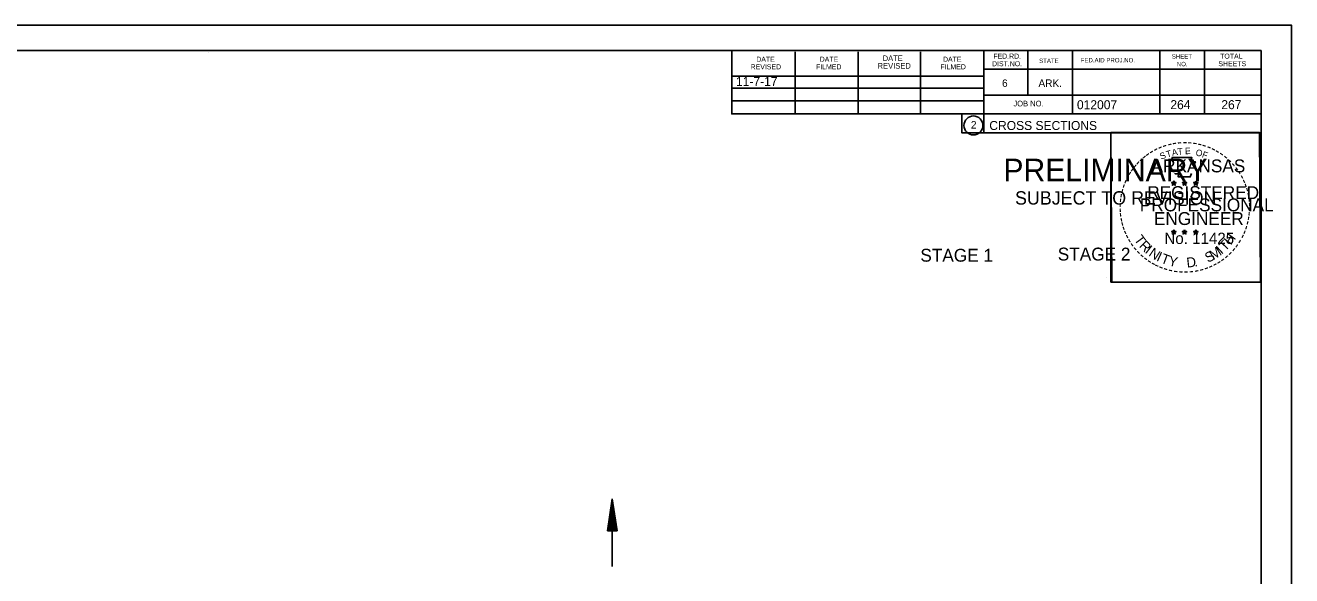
# Model space of a CAD drawing. Extents: x 1374311 to 1383814, y 384102 to 406278.
# Drawn here: x 1382687 to 1382883.8, y 387380.4 to 387465.9 of the extents above; entities that cross this region are included whole.
import ezdxf

# ---------------------------------------------------------------- set-up
doc = ezdxf.new("R2010")
doc.units = 0
for name, color, linetype in [('R_Border', 7, 'Continuous'), ('R_Border PE', 7, 'Continuous'), ('R_Border Prem', 7, 'Continuous'), ('R_Draft', 7, 'Continuous'), ('R_Fin Surface', 7, 'Continuous'), ('R_No Plot', 7, 'Continuous'), ('R_Water', 7, 'Continuous')]:
    doc.layers.add(name, color=color, linetype=linetype)

msp = doc.modelspace()

# ---------------------------------------------------------------- linework, layer by layer
at = {"layer": 'R_Border'}
for p, q in [((1382562.86, 387462.05), (1382879.04, 387462.05)), ((1382796.78, 387452.17), (1382796.78, 387462.05)), ((1382835.94, 387462.05), (1382835.94, 387449.25)), ((1382842.78, 387462.05), (1382842.78, 387455.11)), ((1382849.72, 387462.05), (1382849.72, 387452.17)), ((1382863.3, 387462.05), (1382863.3, 387452.17)), ((1382870.24, 387462.05), (1382870.24, 387452.17)), ((1382879.04, 387256.59), (1382879.04, 387462.05)), ((1382715.38, 387461.79), (1382715.38, 387461.79)), ((1382715.38, 387461.79), (1382715.38, 387461.79)), ((1382806.64, 387452.17), (1382806.64, 387461.85)), ((1382816.4, 387452.17), (1382816.4, 387461.85)), ((1382826.08, 387452.17), (1382826.08, 387461.85)), ((1382879.04, 387459.11), (1382835.94, 387459.11)), ((1382879.04, 387459.13), (1382879.04, 387459.13)), ((1382796.78, 387458.03), (1382835.94, 387458.03)), ((1382796.78, 387456.17), (1382835.94, 387456.17)), ((1382796.78, 387452.17), (1382796.78, 387454.23)), ((1382796.78, 387454.23), (1382835.94, 387454.23)), ((1382879.04, 387455.11), (1382835.94, 387455.11)), ((1382838.9, 387455.11), (1382879.04, 387455.11)), ((1382879.04, 387452.17), (1382796.78, 387452.17)), ((1382835.94, 387449.25), (1382879.04, 387449.25))]:
    msp.add_line(p, q, dxfattribs=at)
msp.add_circle((1382834.33, 387450.39), 1.47, dxfattribs=at)
at = {"layer": 'R_Border PE'}
for p, q in [((1382865.13, 387441.51), (1382865.47, 387441.4)), ((1382865.13, 387441.51), (1382865.38, 387441.46)), ((1382865.13, 387441.51), (1382865.36, 387441.39)), ((1382865.26, 387441.1), (1382865.47, 387441.4)), ((1382865.26, 387441.1), (1382865.38, 387441.34)), ((1382865.26, 387441.1), (1382865.47, 387441.32)), ((1382865.47, 387441.76), (1382865.43, 387441.51)), ((1382865.47, 387441.4), (1382865.47, 387441.76)), ((1382865.47, 387441.76), (1382865.52, 387441.51)), ((1382865.82, 387441.51), (1382865.47, 387441.4)), ((1382865.69, 387441.1), (1382865.47, 387441.4)), ((1382865.69, 387441.1), (1382865.47, 387441.31)), ((1382865.82, 387441.51), (1382865.54, 387441.46)), ((1382865.69, 387441.1), (1382865.55, 387441.39)), ((1382865.82, 387441.51), (1382865.62, 387441.41)), ((1382866.8, 387441.51), (1382867.14, 387441.4)), ((1382866.8, 387441.51), (1382867.05, 387441.46)), ((1382866.8, 387441.51), (1382867.03, 387441.39)), ((1382866.93, 387441.1), (1382867.14, 387441.4)), ((1382866.93, 387441.1), (1382867.05, 387441.34)), ((1382866.93, 387441.1), (1382867.14, 387441.32)), ((1382867.14, 387441.76), (1382867.1, 387441.51)), ((1382867.14, 387441.4), (1382867.14, 387441.76)), ((1382867.14, 387441.76), (1382867.19, 387441.51)), ((1382867.49, 387441.51), (1382867.14, 387441.4)), ((1382867.36, 387441.1), (1382867.14, 387441.4)), ((1382867.36, 387441.1), (1382867.14, 387441.31)), ((1382867.49, 387441.51), (1382867.21, 387441.46)), ((1382867.36, 387441.1), (1382867.22, 387441.39)), ((1382867.49, 387441.51), (1382867.29, 387441.41)), ((1382868.56, 387441.5), (1382868.91, 387441.38)), ((1382868.56, 387441.5), (1382868.81, 387441.45)), ((1382868.56, 387441.5), (1382868.8, 387441.37)), ((1382868.69, 387441.09), (1382868.91, 387441.38)), ((1382868.69, 387441.09), (1382868.82, 387441.33)), ((1382868.69, 387441.09), (1382868.91, 387441.3)), ((1382868.91, 387441.75), (1382868.87, 387441.5)), ((1382868.91, 387441.38), (1382868.91, 387441.75)), ((1382868.91, 387441.75), (1382868.96, 387441.5)), ((1382869.26, 387441.5), (1382868.91, 387441.38)), ((1382869.12, 387441.09), (1382868.91, 387441.38)), ((1382869.12, 387441.09), (1382868.91, 387441.3)), ((1382869.26, 387441.5), (1382868.97, 387441.45)), ((1382869.12, 387441.09), (1382868.98, 387441.38)), ((1382869.26, 387441.5), (1382869.05, 387441.39)), ((1382865.12, 387433.93), (1382865.47, 387433.82)), ((1382865.12, 387433.93), (1382865.37, 387433.89)), ((1382865.12, 387433.93), (1382865.36, 387433.81)), ((1382865.25, 387433.53), (1382865.47, 387433.82)), ((1382865.25, 387433.53), (1382865.38, 387433.77)), ((1382865.25, 387433.53), (1382865.47, 387433.74)), ((1382865.47, 387434.19), (1382865.43, 387433.94)), ((1382865.47, 387433.82), (1382865.47, 387434.19)), ((1382865.47, 387434.19), (1382865.52, 387433.94)), ((1382865.82, 387433.93), (1382865.47, 387433.82)), ((1382865.68, 387433.53), (1382865.47, 387433.82)), ((1382865.68, 387433.53), (1382865.47, 387433.74)), ((1382865.82, 387433.93), (1382865.53, 387433.89)), ((1382865.68, 387433.53), (1382865.55, 387433.82)), ((1382865.82, 387433.93), (1382865.61, 387433.83)), ((1382866.79, 387433.93), (1382867.14, 387433.82)), ((1382866.79, 387433.93), (1382867.04, 387433.89)), ((1382866.79, 387433.93), (1382867.03, 387433.81)), ((1382866.92, 387433.53), (1382867.14, 387433.82)), ((1382866.92, 387433.53), (1382867.05, 387433.77)), ((1382866.92, 387433.53), (1382867.14, 387433.74)), ((1382867.14, 387434.19), (1382867.1, 387433.94)), ((1382867.14, 387433.82), (1382867.14, 387434.19)), ((1382867.14, 387434.19), (1382867.19, 387433.94)), ((1382867.49, 387433.93), (1382867.14, 387433.82)), ((1382867.35, 387433.53), (1382867.14, 387433.82)), ((1382867.35, 387433.53), (1382867.14, 387433.74)), ((1382867.49, 387433.93), (1382867.2, 387433.89)), ((1382867.35, 387433.53), (1382867.22, 387433.82)), ((1382867.49, 387433.93), (1382867.28, 387433.83)), ((1382868.56, 387433.92), (1382868.91, 387433.81)), ((1382868.56, 387433.92), (1382868.81, 387433.88)), ((1382868.56, 387433.92), (1382868.79, 387433.8)), ((1382868.69, 387433.52), (1382868.91, 387433.81)), ((1382868.69, 387433.52), (1382868.82, 387433.76)), ((1382868.69, 387433.52), (1382868.9, 387433.73)), ((1382868.91, 387434.18), (1382868.87, 387433.93)), ((1382869.12, 387433.52), (1382868.9, 387433.73)), ((1382868.91, 387433.81), (1382868.91, 387434.18)), ((1382868.91, 387434.18), (1382868.96, 387433.93)), ((1382869.25, 387433.92), (1382868.91, 387433.81)), ((1382869.12, 387433.52), (1382868.91, 387433.81)), ((1382869.25, 387433.92), (1382868.97, 387433.88)), ((1382869.12, 387433.52), (1382868.98, 387433.81)), ((1382869.25, 387433.92), (1382869.05, 387433.82))]:
    msp.add_line(p, q, dxfattribs=at)
for points in [[(1382865.17, 387445.39), (1382865.44, 387444.56)], [(1382868.68, 387444.46), (1382868.82, 387444.75), (1382868.13, 387444.72), (1382868.28, 387445.39), (1382865.17, 387445.39)], [(1382865.66, 387442.96), (1382865.66, 387442.88), (1382866.22, 387442.86), (1382866.17, 387442.38), (1382868.04, 387442.38), (1382868.24, 387442.92)], [(1382865.47, 387441.76), (1382865.69, 387441.1), (1382865.13, 387441.51), (1382865.82, 387441.51), (1382865.26, 387441.1), (1382865.47, 387441.76)], [(1382867.14, 387441.76), (1382867.36, 387441.1), (1382866.8, 387441.51), (1382867.49, 387441.51), (1382866.93, 387441.1), (1382867.14, 387441.76)], [(1382868.91, 387441.75), (1382869.12, 387441.09), (1382868.56, 387441.5), (1382869.26, 387441.5), (1382868.69, 387441.09), (1382868.91, 387441.75)], [(1382865.47, 387434.19), (1382865.68, 387433.53), (1382865.12, 387433.93), (1382865.82, 387433.93), (1382865.25, 387433.53), (1382865.47, 387434.19)], [(1382867.14, 387434.19), (1382867.35, 387433.53), (1382866.79, 387433.93), (1382867.49, 387433.93), (1382866.92, 387433.53), (1382867.14, 387434.19)], [(1382868.91, 387434.18), (1382869.12, 387433.52), (1382868.56, 387433.92), (1382869.25, 387433.92), (1382868.69, 387433.52), (1382868.91, 387434.18)]]:
    msp.add_lwpolyline(points, dxfattribs=at)
for centre, radius in [((1382865.47, 387441.4), 0.172), ((1382865.47, 387441.4), 0.145), ((1382865.47, 387441.4), 0.116), ((1382865.47, 387441.4), 0.0991), ((1382865.47, 387441.4), 0.0747), ((1382865.47, 387441.4), 0.0495), ((1382865.47, 387441.4), 0.0296), ((1382867.14, 387441.4), 0.172), ((1382867.14, 387441.4), 0.145), ((1382867.14, 387441.4), 0.116), ((1382867.14, 387441.4), 0.0991), ((1382867.14, 387441.4), 0.0747), ((1382867.14, 387441.4), 0.0495), ((1382867.14, 387441.4), 0.0296), ((1382868.91, 387441.38), 0.172), ((1382868.91, 387441.38), 0.145), ((1382868.91, 387441.38), 0.116), ((1382868.91, 387441.38), 0.0991), ((1382868.91, 387441.38), 0.0747), ((1382868.91, 387441.38), 0.0495), ((1382868.91, 387441.38), 0.0296), ((1382865.47, 387433.82), 0.172), ((1382865.47, 387433.82), 0.145), ((1382865.47, 387433.82), 0.116), ((1382865.47, 387433.82), 0.0991), ((1382865.47, 387433.82), 0.0747), ((1382865.47, 387433.82), 0.0495), ((1382865.47, 387433.82), 0.0296), ((1382867.14, 387433.82), 0.172), ((1382867.14, 387433.82), 0.145), ((1382867.14, 387433.82), 0.116), ((1382867.14, 387433.82), 0.0991), ((1382867.14, 387433.82), 0.0747), ((1382867.14, 387433.82), 0.0495), ((1382867.14, 387433.82), 0.0296), ((1382868.91, 387433.81), 0.172), ((1382868.91, 387433.81), 0.145), ((1382868.91, 387433.81), 0.116), ((1382868.91, 387433.81), 0.0991), ((1382868.91, 387433.81), 0.0747), ((1382868.91, 387433.81), 0.0495), ((1382868.91, 387433.81), 0.0296)]:
    msp.add_circle(centre, radius, dxfattribs=at)
at = {"layer": 'R_Draft'}
for p, q in [((1382777.44, 387387.38), (1382778.19, 387392.38)), ((1382777.57, 387387.38), (1382778.19, 387391.55)), ((1382778.94, 387387.38), (1382778.19, 387392.38)), ((1382778.82, 387387.38), (1382778.19, 387391.55)), ((1382777.69, 387387.38), (1382778.19, 387390.69)), ((1382777.82, 387387.38), (1382778.19, 387389.85)), ((1382778.69, 387387.38), (1382778.19, 387390.69)), ((1382778.56, 387387.38), (1382778.19, 387389.85)), ((1382777.44, 387387.38), (1382778.94, 387387.38)), ((1382777.95, 387387.38), (1382778.19, 387389.01)), ((1382778.07, 387387.38), (1382778.19, 387388.17)), ((1382778.44, 387387.38), (1382778.19, 387389.01)), ((1382778.31, 387387.38), (1382778.19, 387388.17))]:
    msp.add_line(p, q, dxfattribs=at)
at = {"layer": 'R_No Plot'}
for p, q in [((1382550.46, 387465.95), (1382883.79, 387465.95)), ((1382855.08, 387426.8), (1382855.08, 387426.8))]:
    msp.add_line(p, q, dxfattribs=at)
for points in [[(1382550.45, 387465.95), (1382883.79, 387465.95), (1382883.79, 387252.61), (1382550.45, 387252.61)], [(1382796.78, 387462.05), (1382796.78, 387452.17), (1382832.51, 387452.17), (1382832.51, 387449.25), (1382855.71, 387449.25), (1382855.71, 387426.04), (1382879.04, 387426.04), (1382879.04, 387256.59), (1382562.86, 387256.59), (1382562.86, 387462.05)], [(1382855.71, 387449.28), (1382878.81, 387449.28), (1382878.93, 387426.04), (1382855.83, 387426.04)]]:
    msp.add_lwpolyline(points, close=True, dxfattribs=at)
at = {"layer": 'R_Water'}
msp.add_line((1382778.19, 387381.87), (1382778.19, 387392.38), dxfattribs=at)

# ---------------------------------------------------------------- texts
at = {"layer": 'R_Border'}
for s, height, p in [('DATE', 0.782, (1382800.58, 387460.29)), ('DATE', 0.782, (1382810.44, 387460.29)), ('REVISED', 0.879, (1382819.44, 387459.21)), ('DATE', 0.879, (1382820.22, 387460.39)), ('DATE', 0.782, (1382829.6, 387460.29)), ('DIST.NO.', 0.782, (1382837.22, 387459.59)), ('FED.RD.', 0.782, (1382837.42, 387460.77)), ('STATE', 0.684, (1382844.54, 387460.09)), ('FED.AID PROJ.NO.', 0.684, (1382851, 387460.19)), ('SHEET', 0.684, (1382865.16, 387460.77)), ('NO.', 0.684, (1382865.94, 387459.59)), ('SHEETS', 0.782, (1382872.4, 387459.59)), ('TOTAL', 0.782, (1382872.68, 387460.77)), ('REVISED', 0.782, (1382799.7, 387459.11)), ('FILMED', 0.782, (1382809.86, 387459.11)), ('FILMED', 0.782, (1382829.2, 387459.11)), ('6', 1.17, (1382838.78, 387456.37)), ('ARK.', 1.172, (1382844.44, 387456.37)), ('JOB NO.', 0.879, (1382840.54, 387453.35)), ('012007', 1.4, (1382850.42, 387452.91)), ('2', 1.17, (1382833.94, 387449.9)), ('CROSS SECTIONS', 1.4, (1382836.8, 387449.68))]:
    msp.add_text(s, height=height, rotation=360, dxfattribs=at).set_placement(p)
at = {"layer": 'R_Border PE'}
for s, height, rotation, p in [('-', 1.6, 34.0636, (1382862.05, 387445.56)), ('-', 1.6, 28.7918, (1382862.65, 387445.93)), ('-', 1.6, 24.3072, (1382863.28, 387446.24)), ('-', 1.6, 19.1761, (1382863.91, 387446.51)), ('T', 1, 16.4036, (1382864.44, 387445.39)), ('-', 1.6, 13.6301, (1382864.66, 387446.75)), ('A', 1, 11.2132, (1382865.26, 387445.65)), ('-', 1.6, 10.2193, (1382865.34, 387446.92)), ('T', 1, 6.0228, (1382866.11, 387445.81)), ('-', 1.6, 5.8968, (1382866.07, 387447.03)), ('-', 1.6, 0.1862, (1382866.84, 387447.1)), ('E', 1, 0.8323, (1382867.22, 387445.92)), ('-', 1.6, 357.743, (1382867.57, 387447.08)), ('-', 1.6, 352.1617, (1382868.31, 387447.03)), ('O', 1, 350.4515, (1382868.82, 387445.71)), ('-', 1.6, 347.2049, (1382869.03, 387446.91)), ('F', 1, 340.0707, (1382869.77, 387445.48)), ('-', 1.6, 342.3362, (1382869.66, 387446.76)), ('-', 1.6, 337.8551, (1382870.4, 387446.54)), ('-', 1.6, 334.1211, (1382871.03, 387446.27)), ('-', 1.6, 329.6409, (1382871.61, 387445.98)), ('-', 1.6, 50.6142, (1382859.71, 387443.4)), ('-', 1.6, 48.423, (1382860.12, 387443.89)), ('-', 1.6, 42.9622, (1382860.56, 387444.37)), ('-', 1.6, 38.9507, (1382861, 387444.78)), ('-', 1.6, 36.2317, (1382861.47, 387445.16)), ('ARKANSAS', 2, 360, (1382862.02, 387443.1)), ('S', 1, 21.594, (1382863.52, 387445.06)), ('-', 1.6, 325.8627, (1382872.25, 387445.62)), ('-', 1.6, 320.5297, (1382872.86, 387445.2)), ('-', 1.6, 315.5786, (1382873.46, 387444.71)), ('-', 1.6, 309.8797, (1382874.03, 387444.16)), ('-', 1.6, 62.8713, (1382858.66, 387441.69)), ('-', 1.6, 58.0706, (1382858.97, 387442.31)), ('-', 1.6, 54.2325, (1382859.3, 387442.84)), ('-', 1.6, 306.6522, (1382874.56, 387443.56)), ('-', 1.4, 303.6753, (1382875.04, 387442.99)), ('-', 1.6, 299.6684, (1382875.36, 387442.38)), ('-', 1.6, 75.461, (1382857.99, 387439.74)), ('-', 1.6, 72.3945, (1382858.18, 387440.45)), ('-', 1.6, 67.7743, (1382858.4, 387441.08)), ('REGISTERED', 2, 360, (1382861.34, 387438.95)), ('DWB', 0.01, 360, (1382865.46, 387441.39)), ('DWB', 0.01, 360, (1382867.13, 387441.39)), ('DWB', 0.01, 360, (1382868.9, 387441.38)), ('-', 1.6, 294.6628, (1382875.68, 387441.77)), ('-', 1.6, 290.5728, (1382875.94, 387441.19)), ('-', 1.6, 285.1233, (1382876.18, 387440.61)), ('-', 1.6, 85.1863, (1382857.78, 387438.34)), ('-', 1.6, 81.2013, (1382857.85, 387439.03)), ('PROFESSIONAL', 2, 360, (1382860.19, 387437.04)), ('-', 1.6, 280.5493, (1382876.38, 387439.87)), ('-', 1.6, 276.5962, (1382876.54, 387439.1)), ('-', 1.6, 94.1959, (1382857.79, 387436.91)), ('-', 1.6, 89.0622, (1382857.75, 387437.63)), ('-', 1.6, 98.9479, (1382857.86, 387436.24)), ('ENGINEER', 2, 360, (1382862.38, 387434.92)), ('-', 1.6, 263.5172, (1382876.61, 387437.08)), ('-', 1.6, 274.3301, (1382876.6, 387438.38)), ('-', 1.6, 269.9407, (1382876.63, 387437.75)), ('-', 1.6, 101.7149, (1382858, 387435.51)), ('-', 1.6, 105.4578, (1382858.16, 387434.91)), ('-', 1.6, 109.0874, (1382858.37, 387434.28)), ('-', 1.6, 252.8681, (1382876.25, 387435.03)), ('-', 1.6, 255.7626, (1382876.43, 387435.75)), ('-', 1.6, 260.9953, (1382876.54, 387436.43)), ('-', 1.6, 114.0643, (1382858.63, 387433.69)), ('-', 1.6, 115.7289, (1382858.93, 387433.07)), ('-', 1.6, 120.4471, (1382859.29, 387432.48)), ('T', 1.54, 306.0406, (1382859.23, 387432.66)), ('R', 1.54, 314.005, (1382859.99, 387431.61)), ('No. 11425', 1.757, 360, (1382864.01, 387431.97)), ('DWB', 0.01, 360, (1382865.46, 387433.82)), ('DWB', 0.01, 360, (1382867.13, 387433.82)), ('DWB', 0.01, 360, (1382868.89, 387433.81)), ('T', 1.54, 46.6444, (1382873.46, 387430.75)), ('H', 1.54, 54.6088, (1382874.35, 387431.7)), ('-', 1.6, 239.0712, (1382875.37, 387432.98)), ('-', 1.6, 244.6197, (1382875.77, 387433.73)), ('-', 1.6, 247.8887, (1382876.03, 387434.36)), ('-', 1.6, 125.8934, (1382859.69, 387431.92)), ('-', 1.6, 130.7181, (1382860.15, 387431.37)), ('-', 1.6, 134.2238, (1382860.67, 387430.83)), ('I', 1.54, 321.9694, (1382860.89, 387430.68)), ('N', 1.54, 326.5002, (1382861.46, 387430.21)), ('I', 1.54, 335.3603, (1382862.67, 387429.42)), ('S', 1.54, 26.9312, (1382870.78, 387429.02)), ('M', 1.54, 32.6563, (1382871.61, 387429.43)), ('I', 1.54, 42.1136, (1382872.9, 387430.28)), ('-', 1.6, 225.7653, (1382874.06, 387431.19)), ('-', 1.6, 231.2538, (1382874.54, 387431.76)), ('-', 1.6, 233.8452, (1382874.97, 387432.32)), ('-', 1.6, 138.9338, (1382861.2, 387430.36)), ('-', 1.6, 144.6463, (1382861.75, 387429.96)), ('-', 1.6, 148.0898, (1382862.31, 387429.58)), ('-', 1.6, 151.5704, (1382862.89, 387429.26)), ('-', 1.6, 154.6002, (1382863.41, 387429.01)), ('T', 1.54, 339.8912, (1382863.33, 387429.1)), ('Y', 1.54, 347.8556, (1382864.55, 387428.65)), ('D', 1.54, 6.3969, (1382867.53, 387428.29)), ('.', 1.54, 13.7642, (1382868.72, 387428.42)), ('-', 1.6, 204.2516, (1382871.27, 387429.16)), ('-', 1.6, 207.3568, (1382871.9, 387429.48)), ('-', 1.6, 212.2491, (1382872.46, 387429.82)), ('-', 1.6, 215.7363, (1382872.99, 387430.21)), ('-', 1.6, 221.0851, (1382873.54, 387430.68)), ('-', 1.6, 158.5612, (1382864.04, 387428.76)), ('-', 1.6, 162.7983, (1382864.72, 387428.55)), ('-', 1.6, 167.5555, (1382865.44, 387428.38)), ('-', 1.6, 173.1155, (1382866.21, 387428.27)), ('-', 1.6, 176.5183, (1382866.96, 387428.22)), ('-', 1.6, 181.5918, (1382867.7, 387428.24)), ('-', 1.6, 185.8167, (1382868.51, 387428.31)), ('-', 1.6, 191.2858, (1382869.25, 387428.45)), ('-', 1.6, 195.4743, (1382869.98, 387428.64)), ('-', 1.6, 200.7184, (1382870.65, 387428.89))]:
    msp.add_text(s, height=height, rotation=rotation, dxfattribs=at).set_placement(p)
at = {"layer": 'R_Border Prem'}
for s, height, p in [('PRELIMINARY', 3.5, (1382838.99, 387441.72)), ('DWB', 0.01, (1382839.74, 387443.56)), ('SUBJECT TO REVISION', 2.0751, (1382840.8, 387438.09))]:
    msp.add_text(s, height=height, rotation=360, dxfattribs=at).set_placement(p)
at = {"layer": 'R_Fin Surface'}
msp.add_text('11-7-17', height=1.4, dxfattribs=at).set_placement((1382797.43, 387456.53))
at = {"layer": 'R_Water'}
for s, p in [('264', (1382864.94, 387452.92)), ('267', (1382872.86, 387452.92))]:
    msp.add_text(s, height=1.4, rotation=360, dxfattribs=at).set_placement(p)
for s, p in [('STAGE 1', (1382826.08, 387429.22)), ('STAGE 2', (1382847.44, 387429.4))]:
    msp.add_text(s, height=2, dxfattribs=at).set_placement(p)

doc.saveas('drawing.dxf')
